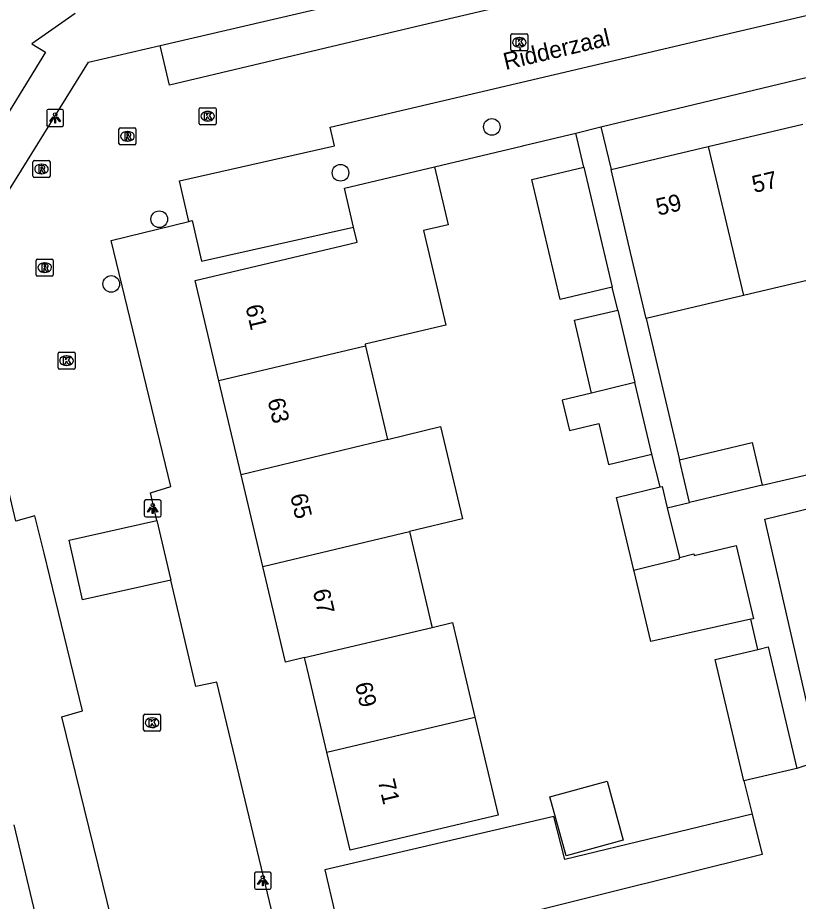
# Model space of a CAD drawing. Extents: x 158038 to 159242, y 380133 to 381214.
# Drawn here: x 158379 to 158424.9, y 381003.1 to 381055.1 of the extents above; entities that cross this region are included whole.
import ezdxf

# ---------------------------------------------------------------- set-up
doc = ezdxf.new("R2010")
doc.units = 0
for name, color, linetype in [('IMGEO_Boom', 7, 'Continuous'), ('IMGEO_Kolk', 7, 'Continuous'), ('IMGEO_Lichtpunt', 7, 'Continuous'), ('IMGEO_Muur', 7, 'Continuous'), ('IMGEO_Openbare_ruimte_label', 7, 'Continuous'), ('IMGEO_Pand', 7, 'Continuous'), ('IMGEO_Pand_nummerreeks', 7, 'Continuous'), ('IMGEO_Parkeervlak_open', 7, 'Continuous'), ('IMGEO_Rijbaan_lokaal_open', 7, 'Continuous'), ('IMGEO_Rioolput', 7, 'Continuous'), ('IMGEO_Voetpad_open', 7, 'Continuous')]:
    doc.layers.add(name, color=color, linetype=linetype)

msp = doc.modelspace()

# ---------------------------------------------------------------- linework, layer by layer
at = {"layer": 'IMGEO_Boom'}
for centre in [(158406.856, 381048.686), (158397.948, 381045.989), (158387.283, 381043.259), (158384.459, 381039.451)]:
    msp.add_circle(centre, 0.489, dxfattribs=at)
at = {"layer": 'IMGEO_Kolk'}
for p, q in [((158407.973, 381053.235), (158407.973, 381054.087)), ((158408.048, 381054.161), (158408.9, 381054.161)), ((158408.461, 381053.941), (158408.486, 381053.941)), ((158408.974, 381054.087), (158408.974, 381053.235)), ((158408.484, 381053.381), (158408.459, 381053.381)), ((158408.9, 381053.161), (158408.048, 381053.161)), ((158389.629, 381048.892), (158389.629, 381049.744)), ((158389.704, 381049.818), (158390.556, 381049.818)), ((158390.117, 381049.598), (158390.142, 381049.598)), ((158390.63, 381049.744), (158390.63, 381048.892)), ((158390.14, 381049.038), (158390.115, 381049.038)), ((158390.556, 381048.818), (158389.704, 381048.818)), ((158381.328, 381034.509), (158381.328, 381035.361)), ((158381.403, 381035.435), (158382.255, 381035.435)), ((158381.816, 381035.215), (158381.841, 381035.215)), ((158382.329, 381035.361), (158382.329, 381034.509)), ((158381.839, 381034.655), (158381.814, 381034.655)), ((158382.255, 381034.435), (158381.403, 381034.435)), ((158386.363, 381013.215), (158386.363, 381014.067)), ((158386.438, 381014.141), (158387.29, 381014.141)), ((158386.851, 381013.921), (158386.876, 381013.921)), ((158387.364, 381014.067), (158387.364, 381013.215)), ((158386.874, 381013.361), (158386.849, 381013.361)), ((158387.29, 381013.141), (158386.438, 381013.141))]:
    msp.add_line(p, q, dxfattribs=at)
for points in [[(158407.973, 381053.235), (158407.973, 381054.087)], [(158408.048, 381054.161), (158408.9, 381054.161)], [(158408.294, 381053.861), (158408.417, 381053.861), (158408.417, 381053.71), (158408.547, 381053.861), (158408.711, 381053.861), (158408.565, 381053.71), (158408.718, 381053.461), (158408.566, 381053.461), (158408.481, 381053.625), (158408.417, 381053.558), (158408.417, 381053.461), (158408.294, 381053.461), (158408.294, 381053.861)], [(158408.974, 381054.087), (158408.974, 381053.235)], [(158408.9, 381053.161), (158408.048, 381053.161)], [(158389.629, 381048.892), (158389.629, 381049.744)], [(158389.704, 381049.818), (158390.556, 381049.818)], [(158390.63, 381049.744), (158390.63, 381048.892)], [(158389.95, 381049.518), (158390.073, 381049.518), (158390.073, 381049.367), (158390.203, 381049.518), (158390.367, 381049.518), (158390.221, 381049.367), (158390.374, 381049.118), (158390.222, 381049.118), (158390.137, 381049.282), (158390.073, 381049.215), (158390.073, 381049.118), (158389.95, 381049.118), (158389.95, 381049.518)], [(158390.556, 381048.818), (158389.704, 381048.818)], [(158381.328, 381034.509), (158381.328, 381035.361)], [(158381.403, 381035.435), (158382.255, 381035.435)], [(158381.649, 381035.135), (158381.772, 381035.135), (158381.772, 381034.984), (158381.902, 381035.135), (158382.066, 381035.135), (158381.92, 381034.984), (158382.073, 381034.735), (158381.921, 381034.735), (158381.836, 381034.899), (158381.772, 381034.832), (158381.772, 381034.735), (158381.649, 381034.735), (158381.649, 381035.135)], [(158382.329, 381035.361), (158382.329, 381034.509)], [(158382.255, 381034.435), (158381.403, 381034.435)], [(158386.363, 381013.215), (158386.363, 381014.067)], [(158386.438, 381014.141), (158387.29, 381014.141)], [(158386.684, 381013.841), (158386.807, 381013.841), (158386.807, 381013.69), (158386.937, 381013.841), (158387.101, 381013.841), (158386.955, 381013.69), (158387.108, 381013.441), (158386.956, 381013.441), (158386.871, 381013.605), (158386.807, 381013.538), (158386.807, 381013.441), (158386.684, 381013.441), (158386.684, 381013.841)], [(158387.364, 381014.067), (158387.364, 381013.215)], [(158387.29, 381013.141), (158386.438, 381013.141)]]:
    msp.add_lwpolyline(points, dxfattribs=at)
for centre, start, end in [((158408.05, 381054.085), 91.552, 178.448), ((158408.05, 381054.085), 91.552, 178.448), ((158408.898, 381054.085), 1.552, 88.448), ((158408.898, 381054.085), 1.552, 88.448), ((158408.05, 381053.237), 181.552, 268.448), ((158408.05, 381053.237), 181.552, 268.448), ((158408.898, 381053.237), 271.552, 358.448), ((158408.898, 381053.237), 271.552, 358.448), ((158389.706, 381049.742), 91.552, 178.448), ((158389.706, 381049.742), 91.552, 178.448), ((158390.554, 381049.742), 1.552, 88.448), ((158390.554, 381049.742), 1.552, 88.448), ((158389.706, 381048.894), 181.552, 268.448), ((158389.706, 381048.894), 181.552, 268.448), ((158390.554, 381048.894), 271.552, 358.448), ((158390.554, 381048.894), 271.552, 358.448), ((158381.405, 381035.359), 91.552, 178.448), ((158381.405, 381035.359), 91.552, 178.448), ((158382.253, 381035.359), 1.552, 88.448), ((158382.253, 381035.359), 1.552, 88.448), ((158381.405, 381034.511), 181.552, 268.448), ((158381.405, 381034.511), 181.552, 268.448), ((158382.253, 381034.511), 271.552, 358.448), ((158382.253, 381034.511), 271.552, 358.448), ((158386.44, 381014.065), 91.552, 178.448), ((158386.44, 381014.065), 91.552, 178.448), ((158387.288, 381014.065), 1.552, 88.448), ((158387.288, 381014.065), 1.552, 88.448), ((158386.44, 381013.217), 181.552, 268.448), ((158386.44, 381013.217), 181.552, 268.448), ((158387.288, 381013.217), 271.552, 358.448), ((158387.288, 381013.217), 271.552, 358.448)]:
    msp.add_arc(centre, 0.0765, start, end, dxfattribs=at)
for centre, major_axis, ratio, start_param, end_param in [((158408.46, 381053.661), (-0.387, 0.002), 0.722429, 4.712389, 7.853982), ((158408.485, 381053.661), (-0.39, 0.002), 0.717154, 1.570796, 4.712389), ((158390.116, 381049.318), (-0.387, 0.002), 0.722429, 4.712389, 7.853982), ((158390.141, 381049.318), (-0.39, 0.002), 0.717154, 1.570796, 4.712389), ((158381.815, 381034.935), (-0.387, 0.002), 0.722429, 4.712389, 7.853982), ((158381.84, 381034.935), (-0.39, 0.002), 0.717154, 1.570796, 4.712389), ((158386.85, 381013.641), (-0.387, 0.002), 0.722429, 4.712389, 7.853982), ((158386.875, 381013.641), (-0.39, 0.002), 0.717154, 1.570796, 4.712389)]:
    msp.add_ellipse(centre, major_axis=major_axis, ratio=ratio, start_param=start_param, end_param=end_param, dxfattribs=at)
at = {"layer": 'IMGEO_Lichtpunt'}
for p, q in [((158380.658, 381049.621), (158380.658, 381048.814)), ((158380.658, 381049.621), (158380.658, 381048.814)), ((158381.56, 381049.716), (158380.752, 381049.716)), ((158381.56, 381049.716), (158380.752, 381049.716)), ((158381.654, 381048.814), (158381.654, 381049.621)), ((158381.654, 381048.814), (158381.654, 381049.621)), ((158380.752, 381048.72), (158381.56, 381048.72)), ((158380.752, 381048.72), (158381.56, 381048.72)), ((158387.3, 381026.744), (158386.492, 381026.744)), ((158387.3, 381026.744), (158386.492, 381026.744)), ((158386.398, 381026.649), (158386.398, 381025.842)), ((158386.398, 381026.649), (158386.398, 381025.842)), ((158387.394, 381025.842), (158387.394, 381026.649)), ((158387.394, 381025.842), (158387.394, 381026.649)), ((158386.492, 381025.748), (158387.3, 381025.748)), ((158386.492, 381025.748), (158387.3, 381025.748)), ((158392.88, 381004.752), (158392.88, 381003.945)), ((158392.88, 381004.752), (158392.88, 381003.945)), ((158393.782, 381004.847), (158392.974, 381004.847)), ((158393.782, 381004.847), (158392.974, 381004.847)), ((158393.876, 381003.945), (158393.876, 381004.752)), ((158393.876, 381003.945), (158393.876, 381004.752)), ((158392.974, 381003.851), (158393.782, 381003.851)), ((158392.974, 381003.851), (158393.782, 381003.851))]:
    msp.add_line(p, q, dxfattribs=at)
for points in [[(158381.032, 381049.285), (158381.071, 381049.257), (158380.883, 381048.995), (158380.845, 381049.022), (158381.032, 381049.285)], [(158381.134, 381049.237), (158381.181, 381049.237), (158381.181, 381048.915), (158381.134, 381048.915), (158381.134, 381049.237)], [(158381.244, 381049.257), (158381.282, 381049.284), (158381.469, 381049.022), (158381.43, 381048.994), (158381.244, 381049.257)], [(158386.772, 381026.313), (158386.811, 381026.285), (158386.623, 381026.023), (158386.585, 381026.05), (158386.772, 381026.313)], [(158386.874, 381026.265), (158386.921, 381026.265), (158386.921, 381025.943), (158386.874, 381025.943), (158386.874, 381026.265)], [(158386.984, 381026.285), (158387.022, 381026.312), (158387.209, 381026.05), (158387.17, 381026.022), (158386.984, 381026.285)], [(158393.254, 381004.416), (158393.293, 381004.388), (158393.105, 381004.126), (158393.067, 381004.153), (158393.254, 381004.416)], [(158393.356, 381004.368), (158393.403, 381004.368), (158393.403, 381004.046), (158393.356, 381004.046), (158393.356, 381004.368)], [(158393.466, 381004.388), (158393.504, 381004.415), (158393.691, 381004.153), (158393.652, 381004.125), (158393.466, 381004.388)]]:
    msp.add_lwpolyline(points, dxfattribs=at)
for centre in [(158381.157, 381049.419), (158386.897, 381026.447), (158393.379, 381004.55)]:
    msp.add_circle(centre, 0.0994, dxfattribs=at)
for centre, start, end in [((158380.752, 381049.621), 90, 180), ((158380.752, 381049.621), 90, 180), ((158381.56, 381049.621), 0, 90), ((158381.56, 381049.621), 0, 90), ((158380.752, 381048.814), 180, 270), ((158380.752, 381048.814), 180, 270), ((158381.56, 381048.814), 270, 0), ((158381.56, 381048.814), 270, 360), ((158386.492, 381026.649), 90, 180), ((158386.492, 381026.649), 90, 180), ((158387.3, 381026.649), 0, 90), ((158387.3, 381026.649), 0, 90), ((158386.492, 381025.842), 180, 270), ((158386.492, 381025.842), 180, 270), ((158387.3, 381025.842), 270, 0), ((158387.3, 381025.842), 270, 360), ((158392.974, 381004.752), 90, 180), ((158392.974, 381004.752), 90, 180), ((158393.782, 381004.752), 0, 90), ((158393.782, 381004.752), 0, 90), ((158392.974, 381003.945), 180, 270), ((158392.974, 381003.945), 180, 270), ((158393.782, 381003.945), 270, 0), ((158393.782, 381003.945), 270, 360)]:
    msp.add_arc(centre, 0.0946, start, end, dxfattribs=at)
at = {"layer": 'IMGEO_Muur'}
msp.add_lwpolyline([(158403.471, 381046.341), (158408.687, 381047.577)], dxfattribs=at)
at = {"layer": 'IMGEO_Pand'}
for points in [[(158382.344, 381055.362), (158379.776, 381053.581), (158380.582, 381053.083), (158377.309, 381047.779)], [(158419.591, 381047.529), (158425.165, 381048.849)], [(158413.872, 381046.175), (158419.591, 381047.529)], [(158419.591, 381047.529), (158421.665, 381038.77)], [(158398.721, 381042.793), (158398.178, 381045.087), (158403.471, 381046.341)], [(158403.471, 381046.341), (158404.28, 381042.929), (158402.827, 381042.586), (158404.142, 381037.024), (158401.899, 381036.493), (158399.396, 381035.9), (158399.421, 381035.796)], [(158413.937, 381039.268), (158410.872, 381038.542), (158409.202, 381045.589), (158412.267, 381046.315)], [(158412.267, 381046.315), (158413.937, 381039.268)], [(158415.946, 381037.415), (158415.024, 381041.31), (158413.872, 381046.175)], [(158390.792, 381033.75), (158389.393, 381039.656), (158398.022, 381041.7), (158398.929, 381041.915), (158398.721, 381042.793)], [(158427.239, 381040.09), (158421.665, 381038.77)], [(158421.665, 381038.77), (158415.946, 381037.415)], [(158412.728, 381033.036), (158411.715, 381037.312), (158414.267, 381037.917)], [(158414.267, 381037.917), (158415.277, 381033.651)], [(158399.421, 381035.796), (158390.792, 381033.75)], [(158399.421, 381035.796), (158400.721, 381030.305)], [(158392.102, 381028.217), (158390.792, 381033.75)], [(158415.277, 381033.651), (158412.728, 381033.036)], [(158416.276, 381029.433), (158415.277, 381033.651)], [(158412.728, 381033.036), (158410.991, 381032.617), (158411.423, 381030.828), (158413.152, 381031.245), (158413.725, 381028.829), (158416.276, 381029.433)], [(158400.721, 381030.305), (158403.835, 381031.059), (158405.122, 381025.626), (158402.005, 381024.887)], [(158400.721, 381030.305), (158399.248, 381029.948), (158392.102, 381028.217)], [(158417.897, 381029.109), (158422.177, 381030.123), (158422.771, 381027.617)], [(158418.491, 381026.603), (158417.897, 381029.109)], [(158393.375, 381022.84), (158392.102, 381028.217)], [(158415.213, 381022.625), (158414.2, 381026.894), (158416.767, 381027.519)], [(158416.767, 381027.519), (158416.869, 381027.544), (158417.176, 381026.283)], [(158422.771, 381027.617), (158418.491, 381026.603)], [(158417.176, 381026.283), (158417.889, 381023.352)], [(158393.375, 381022.84), (158402.005, 381024.887)], [(158402.005, 381024.887), (158403.092, 381020.297), (158403.271, 381019.541), (158403.34, 381019.25)], [(158417.889, 381023.352), (158418.735, 381023.582), (158418.758, 381023.485), (158421.241, 381024.066), (158422.248, 381019.759), (158422.096, 381019.725)], [(158415.213, 381022.625), (158417.907, 381023.278), (158417.889, 381023.352)], [(158395.83, 381017.469), (158394.71, 381017.203), (158393.375, 381022.84)], [(158422.096, 381019.725), (158416.211, 381018.415), (158415.231, 381022.548), (158415.213, 381022.625)], [(158403.34, 381019.25), (158404.541, 381019.535), (158405.858, 381013.973)], [(158395.83, 381017.469), (158403.34, 381019.25)], [(158421.688, 381010.217), (158419.997, 381017.358), (158422.516, 381017.955)], [(158422.516, 381017.955), (158423.116, 381018.097), (158424.808, 381010.955)], [(158397.147, 381011.908), (158396.079, 381016.417), (158395.865, 381017.322), (158395.83, 381017.469)], [(158405.858, 381013.973), (158407.223, 381008.21), (158398.512, 381006.147), (158397.147, 381011.908)], [(158397.147, 381011.908), (158405.858, 381013.973)], [(158424.808, 381010.955), (158421.688, 381010.217)], [(158413.64, 381010.203), (158414.588, 381006.743), (158411.222, 381005.821), (158410.274, 381009.281), (158413.64, 381010.203)], [(158378.726, 381007.641), (158380.072, 381001.957), (158371.806, 381000), (158371.655, 380999.964), (158371.841, 380999.176), (158366.684, 380997.955), (158366.2, 381000), (158365.159, 381004.395), (158367.083, 381004.855)]]:
    msp.add_lwpolyline(points, dxfattribs=at)
at = {"layer": 'IMGEO_Parkeervlak_open'}
for points in [[(158387.343, 381053.48), (158408.115, 381058.316)], [(158413.278, 381048.683), (158435.315, 381053.994)], [(158403.471, 381046.341), (158408.687, 381047.577), (158408.729, 381047.587), (158411.794, 381048.313)], [(158389.015, 381043.132), (158389.227, 381043.184), (158389.773, 381040.782), (158398.721, 381042.793)], [(158422.176, 381008.254), (158411.154, 381005.587), (158410.512, 381008.126), (158397.022, 381004.995), (158397.597, 381002.567)]]:
    msp.add_lwpolyline(points, dxfattribs=at)
at = {"layer": 'IMGEO_Rijbaan_lokaal_open'}
for points in [[(158387.969, 381022.027), (158382.761, 381020.873), (158381.99, 381024.372), (158387.143, 381025.544)], [(158387.143, 381025.544), (158387.224, 381025.199), (158387.874, 381022.434), (158387.969, 381022.027)]]:
    msp.add_lwpolyline(points, dxfattribs=at)
at = {"layer": 'IMGEO_Rioolput'}
for p, q in [((158384.911, 381047.71), (158384.911, 381048.562)), ((158384.986, 381048.636), (158385.838, 381048.636)), ((158385.912, 381048.562), (158385.912, 381047.71)), ((158385.399, 381048.416), (158385.424, 381048.416)), ((158385.838, 381047.636), (158384.986, 381047.636)), ((158385.422, 381047.856), (158385.397, 381047.856)), ((158379.853, 381045.784), (158379.853, 381046.636)), ((158379.928, 381046.71), (158380.78, 381046.71)), ((158380.341, 381046.49), (158380.366, 381046.49)), ((158380.854, 381046.636), (158380.854, 381045.784)), ((158380.364, 381045.93), (158380.339, 381045.93)), ((158380.78, 381045.71), (158379.928, 381045.71)), ((158380.043, 381039.986), (158380.043, 381040.838)), ((158380.118, 381040.912), (158380.97, 381040.912)), ((158381.044, 381040.838), (158381.044, 381039.986)), ((158380.531, 381040.692), (158380.556, 381040.692)), ((158380.97, 381039.912), (158380.118, 381039.912)), ((158380.554, 381040.132), (158380.529, 381040.132))]:
    msp.add_line(p, q, dxfattribs=at)
for points in [[(158384.911, 381047.71), (158384.911, 381048.562)], [(158384.986, 381048.636), (158385.838, 381048.636)], [(158385.912, 381048.562), (158385.912, 381047.71)], [(158385.5, 381048.334), (158385.248, 381048.336), (158385.248, 381047.936)], [(158385.248, 381047.936), (158385.372, 381047.936), (158385.372, 381048.098), (158385.383, 381048.098)], [(158385.426, 381048.255), (158385.372, 381048.255), (158385.372, 381048.174)], [(158385.372, 381048.174), (158385.424, 381048.174)], [(158385.43, 381048.069), (158385.501, 381047.936), (158385.641, 381047.936), (158385.576, 381048.062)], [(158385.838, 381047.636), (158384.986, 381047.636)], [(158379.853, 381045.784), (158379.853, 381046.636)], [(158379.928, 381046.71), (158380.78, 381046.71)], [(158380.854, 381046.636), (158380.854, 381045.784)], [(158380.442, 381046.408), (158380.19, 381046.41), (158380.19, 381046.01)], [(158380.19, 381046.01), (158380.314, 381046.01), (158380.314, 381046.172), (158380.325, 381046.172)], [(158380.368, 381046.329), (158380.314, 381046.329), (158380.314, 381046.248)], [(158380.314, 381046.248), (158380.366, 381046.248)], [(158380.372, 381046.143), (158380.443, 381046.01), (158380.583, 381046.01), (158380.518, 381046.136)], [(158380.78, 381045.71), (158379.928, 381045.71)], [(158380.043, 381039.986), (158380.043, 381040.838)], [(158380.118, 381040.912), (158380.97, 381040.912)], [(158381.044, 381040.838), (158381.044, 381039.986)], [(158380.632, 381040.61), (158380.38, 381040.612), (158380.38, 381040.212)], [(158380.38, 381040.212), (158380.504, 381040.212), (158380.504, 381040.374), (158380.515, 381040.374)], [(158380.558, 381040.531), (158380.504, 381040.531), (158380.504, 381040.45)], [(158380.504, 381040.45), (158380.556, 381040.45)], [(158380.562, 381040.345), (158380.633, 381040.212), (158380.773, 381040.212), (158380.708, 381040.338)], [(158380.97, 381039.912), (158380.118, 381039.912)]]:
    msp.add_lwpolyline(points, dxfattribs=at)
for centre, radius, start, end in [((158384.988, 381048.56), 0.0765, 91.552, 178.448), ((158384.988, 381048.56), 0.0765, 91.552, 178.448), ((158385.836, 381048.56), 0.0765, 1.552, 88.448), ((158385.836, 381048.56), 0.0765, 1.552, 88.448), ((158385.382, 381048.045), 0.0533, 26.0293, 88.6989), ((158385.408, 381048.363), 0.19, 274.7715, 282.9687), ((158385.432, 381048.159), 0.0964, 77.0061, 93.1865), ((158385.446, 381048.216), 0.0378, 276.6634, 79.6772), ((158385.499, 381048.224), 0.109, 350.3612, 89.416), ((158385.497, 381048.224), 0.112, 277.5842, 350.9817), ((158385.481, 381048.009), 0.108, 29.5134, 73.7905), ((158384.988, 381047.712), 0.0765, 181.552, 268.448), ((158384.988, 381047.712), 0.0765, 181.552, 268.448), ((158385.836, 381047.712), 0.0765, 271.552, 358.448), ((158385.836, 381047.712), 0.0765, 271.552, 358.448), ((158379.93, 381046.634), 0.0765, 91.552, 178.448), ((158379.93, 381046.634), 0.0765, 91.552, 178.448), ((158380.778, 381046.634), 0.0765, 1.552, 88.448), ((158380.778, 381046.634), 0.0765, 1.552, 88.448), ((158380.324, 381046.119), 0.0533, 26.0293, 88.6989), ((158380.35, 381046.437), 0.19, 274.7715, 282.9687), ((158380.374, 381046.233), 0.0964, 77.0061, 93.1865), ((158380.388, 381046.29), 0.0378, 276.6634, 79.6772), ((158380.441, 381046.298), 0.109, 350.3612, 89.416), ((158380.439, 381046.298), 0.112, 277.5842, 350.9817), ((158380.423, 381046.083), 0.108, 29.5134, 73.7905), ((158379.93, 381045.786), 0.0765, 181.552, 268.448), ((158379.93, 381045.786), 0.0765, 181.552, 268.448), ((158380.778, 381045.786), 0.0765, 271.552, 358.448), ((158380.778, 381045.786), 0.0765, 271.552, 358.448), ((158380.12, 381040.836), 0.0765, 91.552, 178.448), ((158380.12, 381040.836), 0.0765, 91.552, 178.448), ((158380.968, 381040.836), 0.0765, 1.552, 88.448), ((158380.968, 381040.836), 0.0765, 1.552, 88.448), ((158380.514, 381040.321), 0.0533, 26.0293, 88.6989), ((158380.54, 381040.639), 0.19, 274.7715, 282.9687), ((158380.564, 381040.435), 0.0964, 77.0061, 93.1865), ((158380.578, 381040.492), 0.0378, 276.6634, 79.6772), ((158380.631, 381040.5), 0.109, 350.3612, 89.416), ((158380.629, 381040.5), 0.112, 277.5842, 350.9817), ((158380.613, 381040.285), 0.108, 29.5134, 73.7905), ((158380.12, 381039.988), 0.0765, 181.552, 268.448), ((158380.12, 381039.988), 0.0765, 181.552, 268.448), ((158380.968, 381039.988), 0.0765, 271.552, 358.448), ((158380.968, 381039.988), 0.0765, 271.552, 358.448)]:
    msp.add_arc(centre, radius, start, end, dxfattribs=at)
for centre, major_axis, ratio, start_param, end_param in [((158385.398, 381048.136), (-0.387, 0.002), 0.722429, 4.712389, 7.853982), ((158385.423, 381048.136), (-0.39, 0.002), 0.717154, 1.570796, 4.712389), ((158380.34, 381046.21), (-0.387, 0.002), 0.722429, 4.712389, 7.853982), ((158380.365, 381046.21), (-0.39, 0.002), 0.717154, 1.570796, 4.712389), ((158380.53, 381040.412), (-0.387, 0.002), 0.722429, 4.712389, 7.853982), ((158380.555, 381040.412), (-0.39, 0.002), 0.717154, 1.570796, 4.712389)]:
    msp.add_ellipse(centre, major_axis=major_axis, ratio=ratio, start_param=start_param, end_param=end_param, dxfattribs=at)
at = {"layer": 'IMGEO_Voetpad_open'}
for points in [[(158409.864, 381058.723), (158410.396, 381056.477), (158402.78, 381054.674), (158387.886, 381051.146), (158387.343, 381053.48)], [(158389.015, 381043.132), (158388.476, 381045.507), (158397.589, 381047.573), (158397.338, 381048.68), (158421.489, 381054.349), (158434.514, 381057.407), (158435.315, 381053.994)], [(158384.486, 381002.012), (158381.551, 381013.993), (158382.767, 381014.335), (158381.174, 381020.862), (158380.501, 381023.621), (158379.965, 381025.816), (158378.84, 381025.492), (158376.222, 381036.559), (158375.028, 381036.327), (158374.512, 381038.654), (158383.116, 381052.496), (158387.343, 381053.48)], [(158411.794, 381048.313), (158413.278, 381048.683)], [(158413.278, 381048.683), (158413.872, 381046.175)], [(158412.267, 381046.315), (158411.794, 381048.313)], [(158387.143, 381025.544), (158386.765, 381027.155), (158387.971, 381027.527), (158384.444, 381042.008), (158389.015, 381043.132)], [(158414.267, 381037.917), (158413.937, 381039.268)], [(158415.946, 381037.415), (158417.897, 381029.109)], [(158416.767, 381027.519), (158416.276, 381029.433)], [(158422.771, 381027.617), (158425.464, 381028.252)], [(158417.176, 381026.283), (158418.491, 381026.603)], [(158426.169, 381011.402), (158422.911, 381025.622), (158427.113, 381026.631)], [(158397.597, 381002.567), (158395.782, 381002.093), (158394.123, 381001.659), (158390.663, 381016.019), (158389.439, 381015.767), (158387.969, 381022.027)], [(158422.516, 381017.955), (158422.096, 381019.725)], [(158426.169, 381011.402), (158424.808, 381010.955)], [(158421.688, 381010.217), (158422.176, 381008.254)], [(158422.176, 381008.254), (158422.764, 381005.887), (158413.473, 381003.577), (158403.559, 381001.112), (158398.254, 380999.793), (158397.887, 381001.343), (158397.597, 381002.567)]]:
    msp.add_lwpolyline(points, dxfattribs=at)

# ---------------------------------------------------------------- texts
at = {"layer": 'IMGEO_Openbare_ruimte_label'}
msp.add_text('Ridderzaal', height=1, rotation=13.3553, dxfattribs=at).set_placement((158407.665, 381052.032))
at = {"layer": 'IMGEO_Pand_nummerreeks'}
for s, rotation, p in [('57', 13.3238, (158422.293, 381044.799)), ('59', 13.3238, (158416.647, 381043.462)), ('61', 283.3236, (158392.346, 381038.125)), ('63', 283.3211, (158393.649, 381032.621)), ('65', 283.3211, (158394.978, 381027.008)), ('67', 283.3211, (158396.308, 381021.395)), ('69', 283.3268, (158398.789, 381015.914)), ('71', 283.3259, (158400.138, 381010.215))]:
    msp.add_text(s, height=1, rotation=rotation, dxfattribs=at).set_placement(p)

doc.saveas('drawing.dxf')
